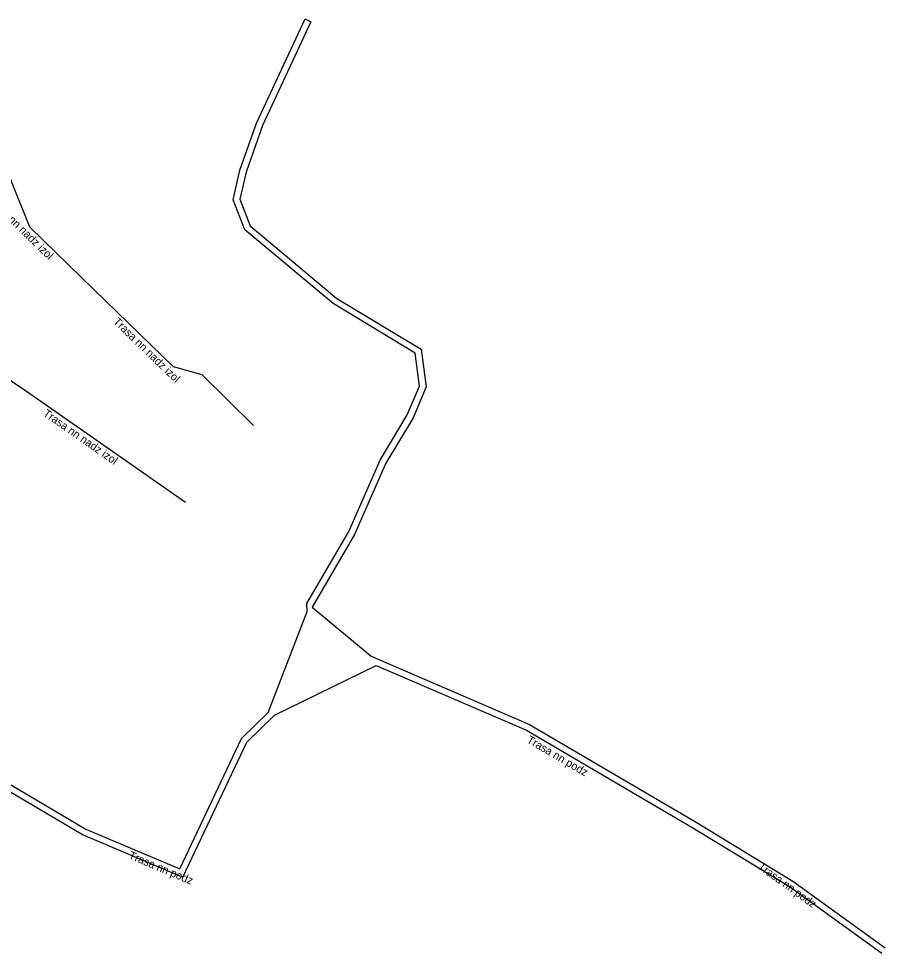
# Model space of a CAD drawing. Extents: x -528089 to -527692, y -1079306 to -1078676.
# Drawn here: x -527914.1 to -527860.3, y -1078930 to -1078871.6 of the extents above; entities that cross this region are included whole.
import ezdxf

# ---------------------------------------------------------------- set-up
doc = ezdxf.new("R2010")
doc.units = 0
doc.layers.add('Popiskový text - Ostatní atributy Trasy', color=7, linetype='Continuous')
doc.layers.add('Spojnice NN', color=7, linetype='Continuous')

msp = doc.modelspace()

# ---------------------------------------------------------------- linework, layer by layer
at = {"layer": 'Spojnice NN'}
for points in [[(-527916.677, -1078918.215), (-527909.86, -1078922.231), (-527903.999, -1078924.711), (-527900.136, -1078916.572), (-527898.485, -1078914.947), (-527896.042, -1078908.633), (-527896.063, -1078908.139), (-527893.438, -1078903.649), (-527891.478, -1078899.188), (-527889.789, -1078896.359), (-527889.025, -1078894.562), (-527889.296, -1078892.502), (-527894.427, -1078889.413), (-527899.927, -1078884.801), (-527900.669, -1078882.926), (-527900.242, -1078881.084), (-527899.205, -1078878.144), (-527896.173, -1078871.618), (-527896, -1078871.72)], [(-527896, -1078871.72), (-527895.822, -1078871.811), (-527898.835, -1078878.296), (-527899.858, -1078881.196), (-527900.251, -1078882.894), (-527899.593, -1078884.559), (-527894.193, -1078889.087), (-527888.924, -1078892.258), (-527888.615, -1078894.618), (-527889.431, -1078896.541), (-527891.122, -1078899.372), (-527893.082, -1078903.831), (-527895.734, -1078908.37), (-527892.039, -1078911.435), (-527882.159, -1078915.701), (-527871.757, -1078921.808), (-527865.709, -1078925.483), (-527859.942, -1078929.651)], [(-527909.343, -1078888.562), (-527913.372, -1078884.635), (-527914.54, -1078881.68)], [(-527899.399, -1078897.027), (-527902.611, -1078893.866), (-527904.396, -1078893.356), (-527909.343, -1078888.562)], [(-527921.47, -1078889.58), (-527913.576, -1078894.886)], [(-527913.576, -1078894.886), (-527903.631, -1078901.821)], [(-527950.354, -1078896.828), (-527954.301, -1078895.655), (-527955.519, -1078897.061), (-527954.162, -1078898.933), (-527947.2, -1078903.574), (-527946.507, -1078903.595), (-527936.72, -1078908.45), (-527936.559, -1078908.751), (-527930.831, -1078911.761), (-527924.996, -1078914.873), (-527917.977, -1078918.408), (-527916.815, -1078918.598), (-527910.04, -1078922.589), (-527903.801, -1078925.229), (-527899.804, -1078916.808), (-527898.093, -1078915.123), (-527891.727, -1078912.006), (-527882.341, -1078916.059), (-527871.963, -1078922.152), (-527865.931, -1078925.817), (-527860.158, -1078929.989)]]:
    msp.add_lwpolyline(points, dxfattribs=at)

# ---------------------------------------------------------------- texts
at = {"layer": 'Popiskový text - Ostatní atributy Trasy'}
for s, rotation, p in [('Trasa nn nadz izol', 315.73457, (-527916.093, -1078882.891)), ('Trasa nn nadz izol', 315.89991, (-527908.189, -1078890.586)), ('Trasa nn nadz izol', 325.10728, (-527912.577, -1078896.376)), ('Trasa nn podz', 329.58249, (-527882.377, -1078916.792)), ('Trasa nn podz', 337.06503, (-527907.234, -1078924.048)), ('Trasa nn podz', 324.14313, (-527867.938, -1078924.674))]:
    msp.add_text(s, height=0.5, rotation=rotation, dxfattribs=at).set_placement(p)

doc.saveas('drawing.dxf')
